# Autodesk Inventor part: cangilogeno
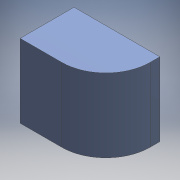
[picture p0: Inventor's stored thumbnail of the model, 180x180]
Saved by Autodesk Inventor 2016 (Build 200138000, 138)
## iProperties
Created: 2016-06
Part Number: cangilogeno
Material: Genérico
Document SubType Name: Modeling
Designer: adm
Density: 1 g/cm^3
Appearance: Valor por defecto
Author: adm
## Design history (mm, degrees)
sketch "Boceto1"
  geometry: L1 (17.5, 11)-(-17.5, 11); L2 (-17.5, 11)-(-17.5, -11); L3 (-17.5, -11)-(-0.5, -11); L4 (17.5, 7)-(17.5, 11); L5 (17.5, 11)-(-17.5, -11); L6 (-17.5, 11)-(17.5, -11); A1 r 18 centre (-0.5, 7) between (-0.5, -11) and (17.5, 7); 1 further point
  constraints: 12 end point, 2 midpoint, 2 parallel, 2 point on circle, 2 point on line, 2 tangent, 1 centre point, 1 horizontal, 1 perpendicular
  dimensions: "d0" = 35 distance of L6.end L2.end; "d1" = 22 distance of L2.end L1.end; "d2" = 18 radius of A1
extrude "Extrusión1" new body sketch "Boceto1" distance "d3" = 30; taper "d4" = 0 deg
feature "Vaciado1" dims "d5" = 1
node "Sólido1"
